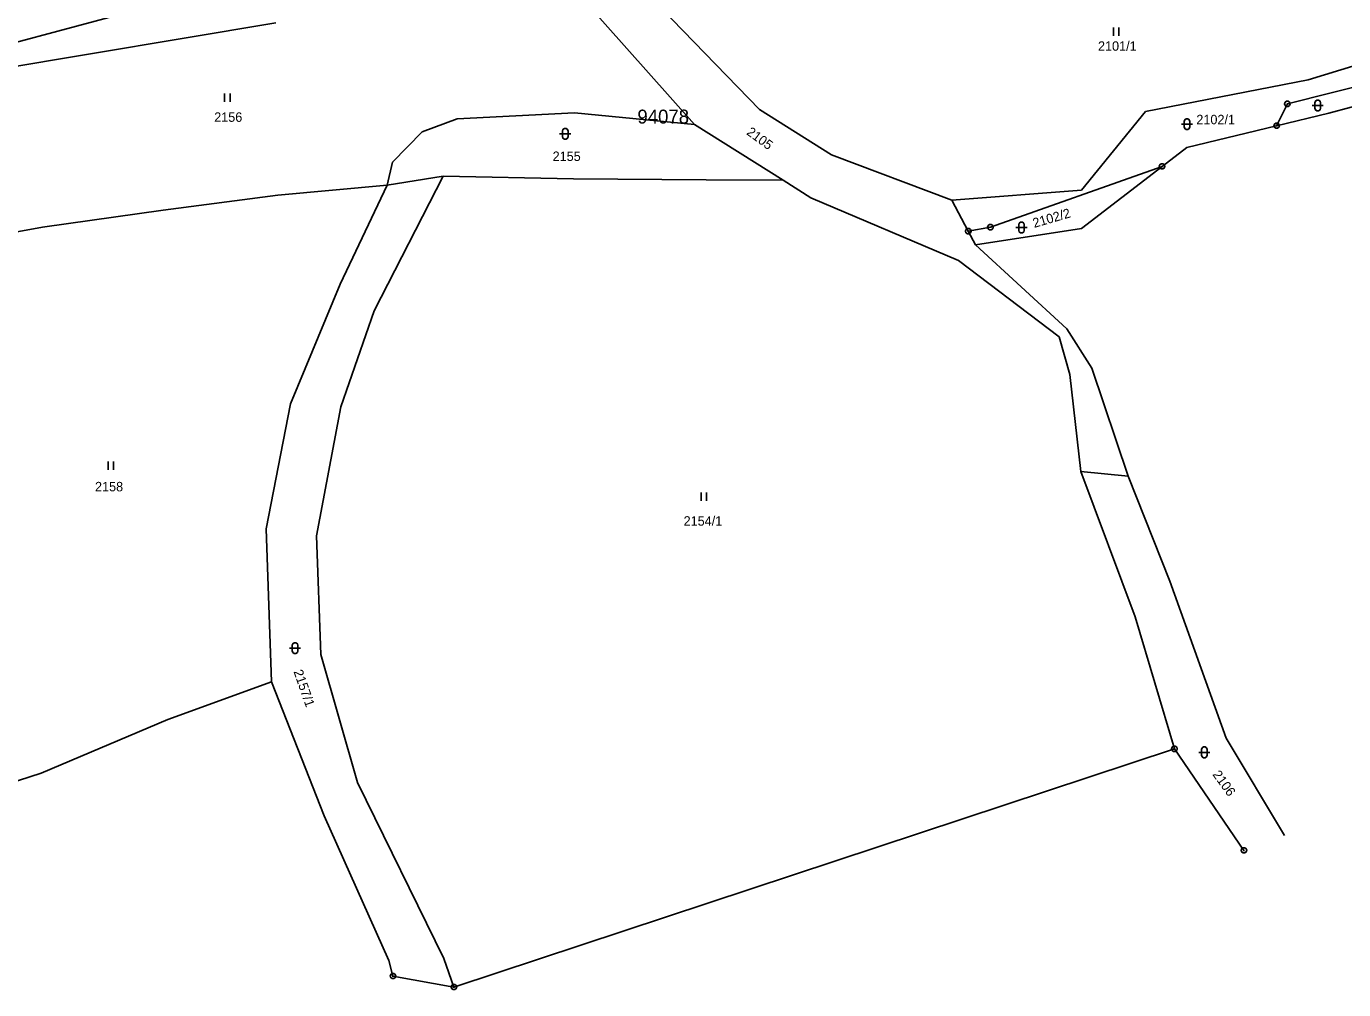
# Model space of a CAD drawing. Extents: x -806774 to -803680, y -1151731 to -1150053.
# Drawn here: x -805353.1 to -805115.9, y -1150851.4 to -1150678 of the extents above; entities that cross this region are included whole.
import ezdxf

# ---------------------------------------------------------------- set-up
doc = ezdxf.new("R2010")
doc.units = 0
for name, color, linetype in [('1', 7, 'Continuous'), ('11', 7, 'Continuous'), ('2', 7, 'Continuous'), ('3', 7, 'Continuous'), ('6', 7, 'Continuous'), ('8', 7, 'Continuous')]:
    doc.layers.add(name, color=color, linetype=linetype)

msp = doc.modelspace()

# ---------------------------------------------------------------- linework, layer by layer
at = {"layer": '1'}
for p, q in [((-805257.77, -1150667.64), (-805232.77, -1150695.74)), ((-805241.07, -1150672.41), (-805221.06, -1150693)), ((-805358.57, -1150685.85), (-805308.19, -1150677.39)), ((-805122.34, -1150687.69), (-805093.75, -1150678.86)), ((-805090.83, -1150683.08), (-805126.05, -1150692)), ((-805118.57, -1150693.67), (-805089.07, -1150685.63)), ((-805151.58, -1150693.36), (-805122.34, -1150687.69)), ((-805126.05, -1150692), (-805127.99, -1150695.94)), ((-805281.82, -1150697.05), (-805275.5, -1150694.72)), ((-805275.5, -1150694.72), (-805254.41, -1150693.59)), ((-805232.77, -1150695.74), (-805254.41, -1150693.59)), ((-805221.06, -1150693), (-805208.12, -1150701.15)), ((-805163.1, -1150707.54), (-805151.58, -1150693.36)), ((-805127.99, -1150695.94), (-805118.57, -1150693.67)), ((-805287.18, -1150702.5), (-805281.82, -1150697.05)), ((-805232.77, -1150695.74), (-805216.83, -1150705.76)), ((-805144.18, -1150699.84), (-805127.99, -1150695.94)), ((-805208.12, -1150701.15), (-805186.47, -1150709.31)), ((-805148.6, -1150703.25), (-805144.18, -1150699.84)), ((-805288.11, -1150706.61), (-805287.18, -1150702.5)), ((-805148.6, -1150703.25), (-805179.51, -1150714.21)), ((-805163.12, -1150714.45), (-805148.6, -1150703.25)), ((-805307.83, -1150708.43), (-805288.11, -1150706.61)), ((-805296.6, -1150724.44), (-805288.11, -1150706.61)), ((-805278.05, -1150705.01), (-805290.48, -1150729.27)), ((-805278.05, -1150705.01), (-805288.11, -1150706.61)), ((-805254.58, -1150705.52), (-805278.05, -1150705.01)), ((-805230.66, -1150705.67), (-805254.58, -1150705.52)), ((-805216.83, -1150705.76), (-805230.66, -1150705.67)), ((-805211.82, -1150708.9), (-805216.83, -1150705.76)), ((-805328.43, -1150711.11), (-805307.83, -1150708.43)), ((-805185.27, -1150720.22), (-805211.82, -1150708.9)), ((-805186.47, -1150709.31), (-805163.1, -1150707.54)), ((-805350.19, -1150714.2), (-805328.43, -1150711.11)), ((-805186.47, -1150709.31), (-805183.51, -1150714.93)), ((-805369.54, -1150717.67), (-805350.19, -1150714.2)), ((-805179.51, -1150714.21), (-805183.51, -1150714.93)), ((-805183.51, -1150714.93), (-805182.21, -1150717.39)), ((-805182.21, -1150717.39), (-805163.12, -1150714.45)), ((-805182.21, -1150717.39), (-805165.75, -1150732.51)), ((-805167.17, -1150733.91), (-805185.27, -1150720.22)), ((-805305.52, -1150746.02), (-805296.6, -1150724.44)), ((-805290.48, -1150729.27), (-805296.43, -1150746.55)), ((-805165.75, -1150732.51), (-805161.27, -1150739.6)), ((-805165.22, -1150740.72), (-805167.17, -1150733.91)), ((-805161.27, -1150739.6), (-805154.7, -1150759.03)), ((-805163.23, -1150758.18), (-805165.22, -1150740.72)), ((-805309.88, -1150768.52), (-805305.52, -1150746.02)), ((-805296.43, -1150746.55), (-805300.86, -1150769.77)), ((-805153.45, -1150784.33), (-805163.23, -1150758.18)), ((-805163.23, -1150758.18), (-805154.7, -1150759.03)), ((-805154.7, -1150759.03), (-805147.2, -1150777.92)), ((-805308.93, -1150796.06), (-805309.88, -1150768.52)), ((-805300.86, -1150769.77), (-805300.07, -1150791.14)), ((-805147.2, -1150777.92), (-805137.09, -1150806.15)), ((-805146.38, -1150808.1), (-805153.45, -1150784.33)), ((-805293.48, -1150814.19), (-805300.07, -1150791.14)), ((-805308.93, -1150796.06), (-805327.59, -1150802.79)), ((-805308.93, -1150796.06), (-805299.46, -1150820.17)), ((-805327.59, -1150802.79), (-805350.4, -1150812.49)), ((-805137.09, -1150806.15), (-805126.55, -1150823.72)), ((-805276.1, -1150850.99), (-805146.38, -1150808.1)), ((-805133.88, -1150826.38), (-805146.38, -1150808.1)), ((-805350.4, -1150812.49), (-805370.96, -1150819.06)), ((-805277.9, -1150845.84), (-805293.48, -1150814.19)), ((-805299.46, -1150820.17), (-805287.83, -1150846.23)), ((-805287.07, -1150849.01), (-805287.83, -1150846.23)), ((-805276.1, -1150850.99), (-805277.9, -1150845.84)), ((-805287.07, -1150849.01), (-805276.1, -1150850.99))]:
    msp.add_line(p, q, dxfattribs=at)
at = {"layer": '3'}
for p, q in [((-805157.37, -1150678.24), (-805157.37, -1150679.74)), ((-805156.37, -1150679.74), (-805156.37, -1150678.24)), ((-805317.39, -1150690.14), (-805317.39, -1150691.64)), ((-805316.39, -1150691.64), (-805316.39, -1150690.14)), ((-805338.36, -1150756.36), (-805338.36, -1150757.86)), ((-805337.36, -1150757.86), (-805337.36, -1150756.36)), ((-805231.6, -1150761.94), (-805231.6, -1150763.44)), ((-805230.6, -1150763.44), (-805230.6, -1150761.94))]:
    msp.add_line(p, q, dxfattribs=at)
for points in [[(-805121.59, -1150692.29), (-805120.32, -1150692.29), (-805119.59, -1150692.29)], [(-805145.13, -1150695.65), (-805143.86, -1150695.65), (-805143.13, -1150695.65)], [(-805257.07, -1150697.4), (-805255.8, -1150697.4), (-805255.07, -1150697.4)], [(-805174.93, -1150714.27), (-805173.66, -1150714.27), (-805172.93, -1150714.27)], [(-805305.7, -1150789.96), (-805304.43, -1150789.96), (-805303.7, -1150789.96)], [(-805142, -1150808.74), (-805140.73, -1150808.74), (-805140, -1150808.74)]]:
    msp.add_lwpolyline(points, dxfattribs=at)
for points in [[(-805121.09, -1150691.79), (-805120.99, -1150691.5), (-805120.74, -1150691.32), (-805120.43, -1150691.32), (-805120.18, -1150691.5), (-805120.08, -1150691.79), (-805120.08, -1150692.79), (-805120.18, -1150693.08), (-805120.43, -1150693.26), (-805120.74, -1150693.26), (-805120.99, -1150693.08), (-805121.09, -1150692.79)], [(-805144.63, -1150695.15), (-805144.53, -1150694.86), (-805144.28, -1150694.68), (-805143.97, -1150694.68), (-805143.72, -1150694.86), (-805143.62, -1150695.15), (-805143.62, -1150696.15), (-805143.72, -1150696.44), (-805143.97, -1150696.62), (-805144.28, -1150696.62), (-805144.53, -1150696.44), (-805144.63, -1150696.15)], [(-805256.57, -1150696.9), (-805256.47, -1150696.61), (-805256.22, -1150696.43), (-805255.91, -1150696.43), (-805255.66, -1150696.61), (-805255.56, -1150696.9), (-805255.56, -1150697.9), (-805255.66, -1150698.19), (-805255.91, -1150698.37), (-805256.22, -1150698.37), (-805256.47, -1150698.19), (-805256.57, -1150697.9)], [(-805174.43, -1150713.77), (-805174.33, -1150713.48), (-805174.08, -1150713.3), (-805173.77, -1150713.3), (-805173.52, -1150713.48), (-805173.42, -1150713.77), (-805173.42, -1150714.77), (-805173.52, -1150715.06), (-805173.77, -1150715.24), (-805174.08, -1150715.24), (-805174.33, -1150715.06), (-805174.43, -1150714.77)], [(-805305.2, -1150789.46), (-805305.1, -1150789.17), (-805304.85, -1150788.99), (-805304.54, -1150788.99), (-805304.29, -1150789.17), (-805304.19, -1150789.46), (-805304.19, -1150790.46), (-805304.29, -1150790.75), (-805304.54, -1150790.93), (-805304.85, -1150790.93), (-805305.1, -1150790.75), (-805305.2, -1150790.46)], [(-805141.5, -1150808.24), (-805141.4, -1150807.95), (-805141.15, -1150807.77), (-805140.84, -1150807.77), (-805140.59, -1150807.95), (-805140.49, -1150808.24), (-805140.49, -1150809.24), (-805140.59, -1150809.53), (-805140.84, -1150809.71), (-805141.15, -1150809.71), (-805141.4, -1150809.53), (-805141.5, -1150809.24)]]:
    msp.add_lwpolyline(points, close=True, dxfattribs=at)
at = {"layer": '6'}
msp.add_line((-805358.86, -1150681.97), (-805329.72, -1150674.16), dxfattribs=at)
at = {"layer": '8'}
for p, q in [((-805126.17, -1150692), (-805125.93, -1150692)), ((-805128.11, -1150695.94), (-805127.87, -1150695.94)), ((-805148.72, -1150703.25), (-805148.48, -1150703.25)), ((-805183.63, -1150714.93), (-805183.39, -1150714.93)), ((-805179.63, -1150714.21), (-805179.39, -1150714.21)), ((-805146.5, -1150808.1), (-805146.26, -1150808.1)), ((-805134, -1150826.38), (-805133.76, -1150826.38)), ((-805287.19, -1150849.01), (-805286.95, -1150849.01)), ((-805276.22, -1150850.99), (-805275.98, -1150850.99))]:
    msp.add_line(p, q, dxfattribs=at)
for points in [[(-805125.9, -1150691.52), (-805125.65, -1150691.7), (-805125.55, -1150691.99), (-805125.65, -1150692.28), (-805125.9, -1150692.46), (-805126.21, -1150692.46), (-805126.46, -1150692.28), (-805126.56, -1150691.99), (-805126.46, -1150691.7), (-805126.21, -1150691.52)], [(-805127.84, -1150695.46), (-805127.59, -1150695.64), (-805127.49, -1150695.93), (-805127.59, -1150696.22), (-805127.84, -1150696.4), (-805128.15, -1150696.4), (-805128.4, -1150696.22), (-805128.5, -1150695.93), (-805128.4, -1150695.64), (-805128.15, -1150695.46)], [(-805148.45, -1150702.77), (-805148.2, -1150702.95), (-805148.1, -1150703.24), (-805148.2, -1150703.53), (-805148.45, -1150703.71), (-805148.76, -1150703.71), (-805149.01, -1150703.53), (-805149.11, -1150703.24), (-805149.01, -1150702.95), (-805148.76, -1150702.77)], [(-805179.36, -1150713.73), (-805179.11, -1150713.91), (-805179.01, -1150714.2), (-805179.11, -1150714.49), (-805179.36, -1150714.67), (-805179.67, -1150714.67), (-805179.92, -1150714.49), (-805180.02, -1150714.2), (-805179.92, -1150713.91), (-805179.67, -1150713.73)], [(-805183.36, -1150714.45), (-805183.11, -1150714.63), (-805183.01, -1150714.92), (-805183.11, -1150715.21), (-805183.36, -1150715.39), (-805183.67, -1150715.39), (-805183.92, -1150715.21), (-805184.02, -1150714.92), (-805183.92, -1150714.63), (-805183.67, -1150714.45)], [(-805146.23, -1150807.62), (-805145.98, -1150807.8), (-805145.88, -1150808.09), (-805145.98, -1150808.38), (-805146.23, -1150808.56), (-805146.54, -1150808.56), (-805146.79, -1150808.38), (-805146.89, -1150808.09), (-805146.79, -1150807.8), (-805146.54, -1150807.62)], [(-805133.73, -1150825.9), (-805133.48, -1150826.08), (-805133.38, -1150826.37), (-805133.48, -1150826.66), (-805133.73, -1150826.84), (-805134.04, -1150826.84), (-805134.29, -1150826.66), (-805134.39, -1150826.37), (-805134.29, -1150826.08), (-805134.04, -1150825.9)], [(-805286.92, -1150848.53), (-805286.67, -1150848.71), (-805286.57, -1150849), (-805286.67, -1150849.29), (-805286.92, -1150849.47), (-805287.23, -1150849.47), (-805287.48, -1150849.29), (-805287.58, -1150849), (-805287.48, -1150848.71), (-805287.23, -1150848.53)], [(-805275.95, -1150850.51), (-805275.7, -1150850.69), (-805275.6, -1150850.98), (-805275.7, -1150851.27), (-805275.95, -1150851.45), (-805276.26, -1150851.45), (-805276.51, -1150851.27), (-805276.61, -1150850.98), (-805276.51, -1150850.69), (-805276.26, -1150850.51)]]:
    msp.add_lwpolyline(points, close=True, dxfattribs=at)

# ---------------------------------------------------------------- texts
at = {"layer": '11'}
msp.add_text('94078', height=2.5, dxfattribs=at).set_placement((-805243.07, -1150695.54))
at = {"layer": '2'}
for s, p in [('2101/1', (-805160.15, -1150682.44)), ('2156', (-805319.26, -1150695.23)), ('2102/1', (-805142.44, -1150695.67)), ('2155', (-805258.33, -1150702.28)), ('2158', (-805340.71, -1150761.75)), ('2154/1', (-805234.75, -1150767.93))]:
    msp.add_text(s, height=1.7, dxfattribs=at).set_placement(p)
for s, rotation, p in [('2105', 324.0076, (-805223.56, -1150697.4)), ('2102/2', 16.2147, (-805171.62, -1150714.33)), ('2157/1', 289.2864, (-805305, -1150794.18)), ('2106', 306.0168, (-805139.61, -1150812.73))]:
    msp.add_text(s, height=1.7, rotation=rotation, dxfattribs=at).set_placement(p)

doc.saveas('drawing.dxf')
